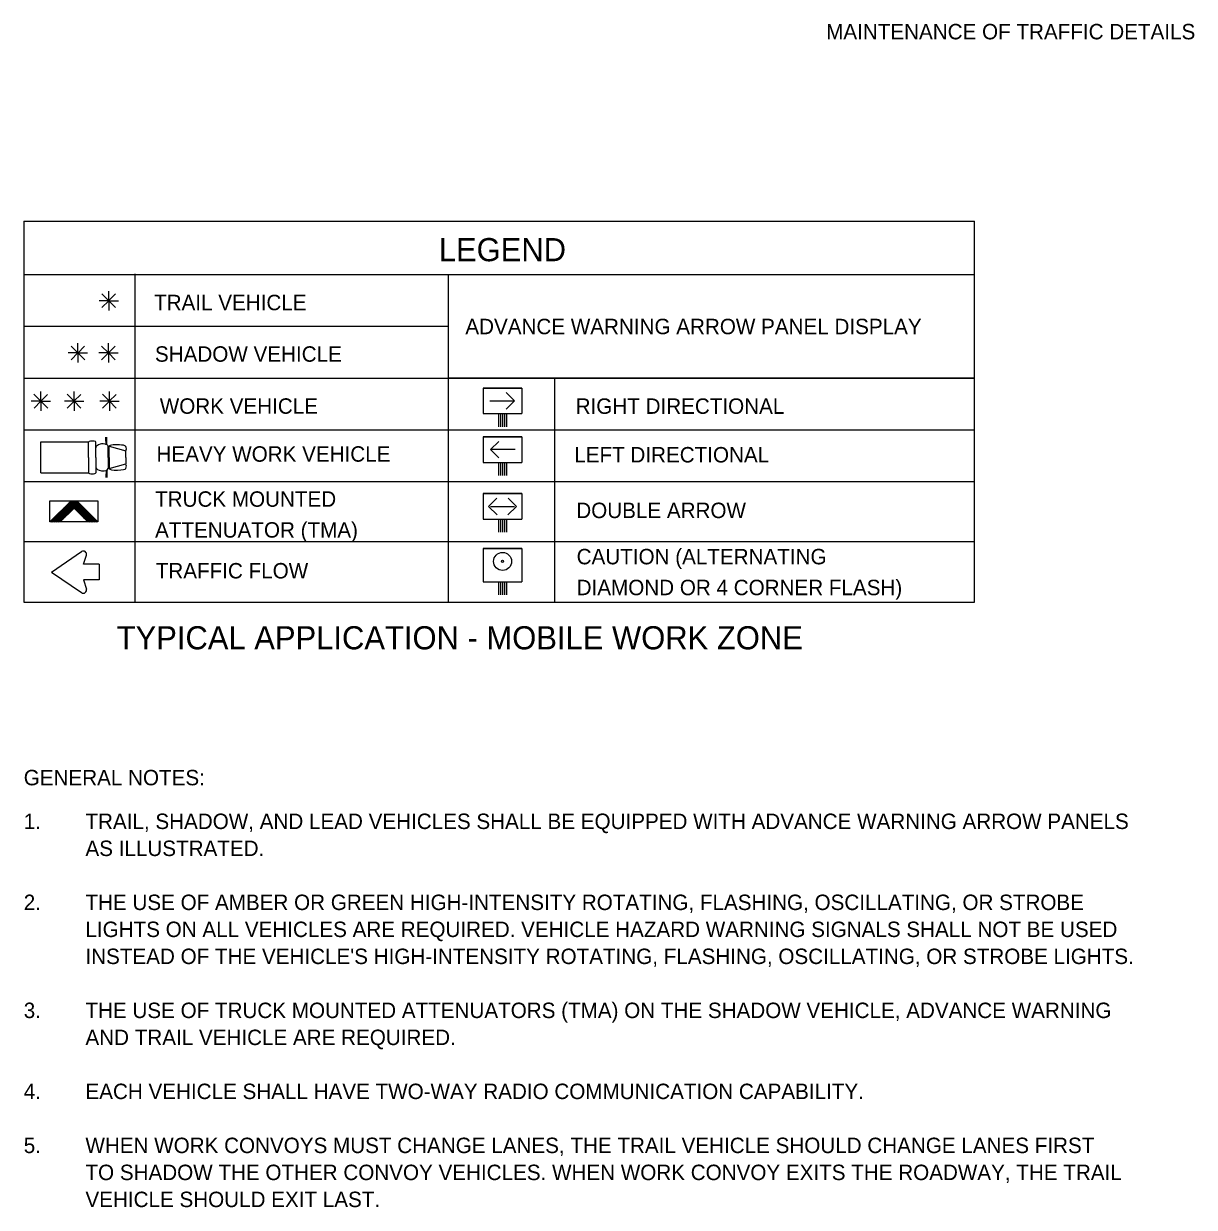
# Model space of a CAD drawing. Extents: x 1373848 to 1374003, y 380642 to 381248.
# Drawn here: x 1373956.39 to 1374001.91, y 381031.39 to 381077.41 of the extents above; entities that cross this region are included whole.
import ezdxf

# ---------------------------------------------------------------- set-up
doc = ezdxf.new("R2010")
doc.units = 0
doc.layers.add('G-ANNO-TEXT', color=7, linetype='Continuous')
doc.layers.add('Working Level 1', color=7, linetype='Continuous')

msp = doc.modelspace()

# ---------------------------------------------------------------- linework, layer by layer
at = {"layer": 'Working Level 1'}
for p, q in [((1373956.388, 381069.735), (1373956.388, 381054.914)), ((1373956.388, 381069.735), (1373993.355, 381069.735)), ((1373993.355, 381054.914), (1373993.355, 381069.735)), ((1373956.388, 381067.655), (1373993.355, 381067.655)), ((1373960.716, 381067.69), (1373960.716, 381054.914)), ((1373960.716, 381067.69), (1373960.716, 381054.914)), ((1373972.892, 381067.655), (1373972.892, 381054.914)), ((1373959.694, 381066.64), (1373959.694, 381067.017)), ((1373959.694, 381066.64), (1373959.318, 381066.64)), ((1373959.694, 381066.64), (1373959.428, 381066.906)), ((1373959.694, 381066.64), (1373959.428, 381066.374)), ((1373959.688, 381066.635), (1373959.954, 381066.901)), ((1373959.694, 381066.64), (1373959.96, 381066.374)), ((1373959.694, 381066.64), (1373959.694, 381066.264)), ((1373959.694, 381066.64), (1373960.07, 381066.64)), ((1373956.388, 381065.644), (1373972.892, 381065.644)), ((1373958.496, 381064.607), (1373958.23, 381064.873)), ((1373958.491, 381064.602), (1373958.758, 381064.868)), ((1373958.496, 381064.607), (1373958.496, 381064.984)), ((1373959.68, 381064.607), (1373959.413, 381064.873)), ((1373959.674, 381064.602), (1373959.941, 381064.868)), ((1373959.68, 381064.607), (1373959.68, 381064.984)), ((1373958.496, 381064.607), (1373958.12, 381064.608)), ((1373958.496, 381064.607), (1373958.231, 381064.341)), ((1373958.496, 381064.607), (1373958.763, 381064.341)), ((1373958.496, 381064.607), (1373958.496, 381064.231)), ((1373958.496, 381064.607), (1373958.873, 381064.607)), ((1373959.68, 381064.607), (1373959.304, 381064.607)), ((1373959.68, 381064.607), (1373959.414, 381064.341)), ((1373959.68, 381064.607), (1373959.946, 381064.341)), ((1373959.68, 381064.607), (1373959.68, 381064.231)), ((1373959.68, 381064.607), (1373960.056, 381064.607)), ((1373956.388, 381063.633), (1373993.355, 381063.633)), ((1373993.355, 381063.633), (1373972.892, 381063.633)), ((1373977.029, 381063.633), (1373977.029, 381054.913)), ((1373957.056, 381062.734), (1373956.789, 381063)), ((1373957.05, 381062.728), (1373957.316, 381062.994)), ((1373957.056, 381062.734), (1373957.056, 381063.11)), ((1373958.345, 381062.734), (1373958.078, 381063)), ((1373958.339, 381062.728), (1373958.605, 381062.994)), ((1373958.345, 381062.734), (1373958.345, 381063.11)), ((1373959.719, 381062.734), (1373959.453, 381063)), ((1373959.713, 381062.728), (1373959.98, 381062.994)), ((1373959.719, 381062.734), (1373959.719, 381063.11)), ((1373974.256, 381063.243), (1373974.256, 381062.248)), ((1373975.761, 381063.243), (1373974.256, 381063.243)), ((1373974.256, 381063.243), (1373975.76, 381063.243)), ((1373975.473, 381062.746), (1373975.154, 381063.065)), ((1373975.761, 381063.243), (1373975.761, 381062.248)), ((1373957.056, 381062.734), (1373956.68, 381062.734)), ((1373957.056, 381062.734), (1373956.79, 381062.468)), ((1373957.056, 381062.734), (1373957.321, 381062.468)), ((1373957.056, 381062.734), (1373957.056, 381062.357)), ((1373957.056, 381062.734), (1373957.432, 381062.734)), ((1373958.345, 381062.734), (1373957.969, 381062.734)), ((1373958.345, 381062.734), (1373958.079, 381062.468)), ((1373958.345, 381062.734), (1373958.611, 381062.468)), ((1373958.345, 381062.734), (1373958.345, 381062.357)), ((1373958.345, 381062.734), (1373958.721, 381062.734)), ((1373959.719, 381062.734), (1373959.343, 381062.734)), ((1373959.719, 381062.734), (1373959.453, 381062.468)), ((1373959.719, 381062.734), (1373959.985, 381062.468)), ((1373959.719, 381062.734), (1373959.719, 381062.357)), ((1373959.719, 381062.734), (1373960.095, 381062.734)), ((1373974.51, 381062.746), (1373975.473, 381062.746)), ((1373975.473, 381062.746), (1373975.146, 381062.419)), ((1373974.256, 381062.248), (1373975.761, 381062.248)), ((1373974.857, 381062.248), (1373974.857, 381061.741)), ((1373974.932, 381062.248), (1373974.932, 381061.741)), ((1373975.008, 381062.248), (1373975.008, 381061.741)), ((1373975.083, 381062.248), (1373975.083, 381061.741)), ((1373975.159, 381062.248), (1373975.159, 381061.741)), ((1373956.388, 381061.622), (1373993.355, 381061.622)), ((1373956.388, 381061.622), (1373972.885, 381061.622)), ((1373957.056, 381061.147), (1373958.911, 381061.147)), ((1373957.056, 381059.947), (1373957.056, 381061.147)), ((1373958.911, 381060.547), (1373958.911, 381061.147)), ((1373959.195, 381060.547), (1373959.195, 381061.147)), ((1373959.578, 381061.182), (1373959.578, 381061.328)), ((1373959.602, 381061.041), (1373959.602, 381061.328)), ((1373959.621, 381061.041), (1373959.621, 381061.328)), ((1373974.256, 381061.35), (1373974.256, 381060.355)), ((1373975.761, 381061.35), (1373974.256, 381061.35)), ((1373974.256, 381061.35), (1373975.76, 381061.35)), ((1373974.542, 381060.853), (1373974.862, 381061.172)), ((1373975.761, 381061.35), (1373975.761, 381060.355)), ((1373958.911, 381060.547), (1373958.911, 381059.947)), ((1373959.195, 381060.547), (1373959.195, 381059.947)), ((1373959.672, 381060.547), (1373959.672, 381060.978)), ((1373959.672, 381060.547), (1373959.672, 381060.115)), ((1373959.711, 381060.978), (1373960.36, 381060.802)), ((1373959.711, 381060.547), (1373959.711, 381060.978)), ((1373959.711, 381060.547), (1373959.711, 381060.115)), ((1373960.36, 381060.547), (1373960.36, 381060.802)), ((1373960.36, 381060.547), (1373960.36, 381060.292)), ((1373975.505, 381060.853), (1373974.542, 381060.853)), ((1373974.542, 381060.853), (1373974.87, 381060.525)), ((1373959.711, 381060.115), (1373960.36, 381060.292)), ((1373974.256, 381060.355), (1373975.761, 381060.355)), ((1373974.857, 381060.355), (1373974.857, 381059.848)), ((1373974.932, 381060.355), (1373974.932, 381059.848)), ((1373975.008, 381060.355), (1373975.008, 381059.848)), ((1373975.083, 381060.355), (1373975.083, 381059.848)), ((1373975.159, 381060.355), (1373975.159, 381059.848)), ((1373957.056, 381059.947), (1373958.911, 381059.947)), ((1373959.578, 381059.912), (1373959.578, 381059.764)), ((1373959.602, 381060.052), (1373959.602, 381059.764)), ((1373959.621, 381060.052), (1373959.621, 381059.764)), ((1373956.388, 381059.612), (1373993.355, 381059.612)), ((1373957.407, 381058.039), (1373958.218, 381058.851)), ((1373959.27, 381058.044), (1373958.467, 381058.847)), ((1373974.256, 381059.141), (1373974.256, 381058.146)), ((1373975.761, 381059.141), (1373974.256, 381059.141)), ((1373974.256, 381059.141), (1373975.76, 381059.141)), ((1373974.467, 381058.644), (1373974.787, 381058.963)), ((1373975.549, 381058.644), (1373975.229, 381058.963)), ((1373975.761, 381059.141), (1373975.761, 381058.146)), ((1373957.813, 381058.039), (1373958.345, 381058.574)), ((1373958.88, 381058.039), (1373958.345, 381058.574)), ((1373974.467, 381058.644), (1373974.794, 381058.316)), ((1373974.542, 381058.644), (1373975.473, 381058.644)), ((1373975.549, 381058.644), (1373975.221, 381058.316)), ((1373974.256, 381058.146), (1373975.761, 381058.146)), ((1373974.857, 381058.146), (1373974.857, 381057.64)), ((1373974.932, 381058.146), (1373974.932, 381057.64)), ((1373975.008, 381058.146), (1373975.008, 381057.64)), ((1373975.083, 381058.146), (1373975.083, 381057.64)), ((1373975.159, 381058.146), (1373975.159, 381057.64)), ((1373956.388, 381057.275), (1373993.355, 381057.275)), ((1373957.475, 381056.087), (1373958.638, 381056.885)), ((1373974.256, 381057), (1373974.256, 381055.706)), ((1373975.761, 381057), (1373974.256, 381057)), ((1373974.256, 381057), (1373975.76, 381057)), ((1373975.761, 381057), (1373975.761, 381055.706)), ((1373958.711, 381056.392), (1373958.825, 381056.745)), ((1373957.475, 381056.087), (1373958.638, 381055.29)), ((1373959.318, 381056.392), (1373958.711, 381056.392)), ((1373959.318, 381056.392), (1373959.318, 381055.783)), ((1373959.318, 381055.783), (1373958.711, 381055.783)), ((1373958.711, 381055.783), (1373958.825, 381055.43)), ((1373974.256, 381055.706), (1373975.761, 381055.706)), ((1373974.857, 381055.706), (1373974.857, 381055.199)), ((1373974.932, 381055.706), (1373974.932, 381055.199)), ((1373975.008, 381055.706), (1373975.008, 381055.199)), ((1373975.083, 381055.706), (1373975.083, 381055.199)), ((1373975.159, 381055.706), (1373975.159, 381055.199)), ((1373956.388, 381054.914), (1373993.355, 381054.914))]:
    msp.add_line(p, q, dxfattribs=at)
msp.add_lwpolyline([(1373959.27, 381058.853), (1373959.27, 381058.039), (1373957.407, 381058.039), (1373957.407, 381058.853)], close=True, dxfattribs=at)
for points in [[(1373957.448, 381058.08), (1373958.579, 381058.733)], [(1373957.548, 381058.18), (1373958.553, 381058.76)], [(1373957.648, 381058.281), (1373958.526, 381058.787)], [(1373957.749, 381058.381), (1373958.499, 381058.814)], [(1373957.849, 381058.481), (1373958.472, 381058.841)], [(1373957.949, 381058.581), (1373958.41, 381058.848)], [(1373958.049, 381058.682), (1373958.338, 381058.849)], [(1373958.148, 381058.781), (1373958.268, 381058.85)], [(1373958.357, 381058.563), (1373958.606, 381058.707)], [(1373957.451, 381058.039), (1373958.304, 381058.532)], [(1373957.524, 381058.039), (1373958.209, 381058.435)], [(1373957.597, 381058.039), (1373958.114, 381058.337)], [(1373958.384, 381058.536), (1373958.633, 381058.68)], [(1373958.411, 381058.509), (1373958.66, 381058.652)], [(1373958.438, 381058.482), (1373958.687, 381058.626)], [(1373958.465, 381058.455), (1373958.714, 381058.599)], [(1373958.492, 381058.428), (1373958.741, 381058.572)], [(1373958.518, 381058.401), (1373958.767, 381058.545)], [(1373958.545, 381058.375), (1373958.794, 381058.518)], [(1373958.572, 381058.347), (1373958.82, 381058.491)], [(1373958.599, 381058.321), (1373958.848, 381058.464)], [(1373958.626, 381058.294), (1373958.874, 381058.437)], [(1373958.653, 381058.267), (1373958.901, 381058.41)], [(1373958.68, 381058.24), (1373958.928, 381058.383)], [(1373958.706, 381058.213), (1373958.955, 381058.356)], [(1373958.733, 381058.186), (1373958.982, 381058.329)], [(1373958.76, 381058.159), (1373959.008, 381058.303)], [(1373958.787, 381058.132), (1373959.035, 381058.276)], [(1373958.814, 381058.105), (1373959.062, 381058.248)], [(1373957.671, 381058.039), (1373958.018, 381058.239)], [(1373957.745, 381058.039), (1373957.922, 381058.142)], [(1373957.818, 381058.039), (1373957.826, 381058.044)], [(1373958.84, 381058.078), (1373959.089, 381058.222)], [(1373958.868, 381058.052), (1373959.115, 381058.194)], [(1373958.919, 381058.039), (1373959.143, 381058.168)], [(1373958.993, 381058.039), (1373959.169, 381058.141)], [(1373959.067, 381058.039), (1373959.196, 381058.114)], [(1373959.14, 381058.039), (1373959.223, 381058.087)], [(1373959.214, 381058.039), (1373959.249, 381058.06)]]:
    msp.add_lwpolyline(points, dxfattribs=at)
for radius in [0.351, 0.0437]:
    msp.add_circle((1373975.008, 381056.503), radius, dxfattribs=at)
for centre, radius, start, end in [((1373960.201, 381060.886), 0.18, 331.8801, 28.1199), ((1373960.201, 381060.207), 0.18, 331.8801, 28.1199), ((1373958.708, 381056.784), 0.123, 342.1824, 124.4455), ((1373958.708, 381055.391), 0.123, 235.5546, 17.8176)]:
    msp.add_arc(centre, radius, start, end, dxfattribs=at)
for centre, major_axis, ratio, start_param, end_param in [((1373959.053, 381061.146), (0.142, 0), 0.269913, 0, 3.141593), ((1373959.433, 381060.949), (0.238, 0.029), 0.503092, 0, 3.141593), ((1373960.035, 381060.974), (0.324, -0.004), 0.2034, 0, 3.141593), ((1373959.433, 381060.144), (0.238, -0.029), 0.503092, 3.141593, 6.283185), ((1373960.035, 381060.118), (0.324, 0.004), 0.2034, 3.141593, 6.283185), ((1373959.053, 381059.947), (0.142, 0), 0.269913, 3.141593, 6.283185)]:
    msp.add_ellipse(centre, major_axis=major_axis, ratio=ratio, start_param=start_param, end_param=end_param, dxfattribs=at)

# ---------------------------------------------------------------- texts
at = {"layer": 'G-ANNO-TEXT'}
msp.add_text('MAINTENANCE OF TRAFFIC DETAILS', height=0.6, dxfattribs=at).set_placement((1373987.593, 381076.802))
at = {"layer": 'Working Level 1'}
for s, height, p in [('LEGEND', 0.9, (1373972.529, 381068.175)), ('TRAIL VEHICLE', 0.6, (1373961.458, 381066.27)), ('ADVANCE WARNING ARROW PANEL DISPLAY', 0.6, (1373973.562, 381065.337)), ('SHADOW VEHICLE', 0.6, (1373961.493, 381064.267)), ('WORK VEHICLE', 0.6, (1373961.68, 381062.244)), ('RIGHT DIRECTIONAL', 0.6, (1373977.853, 381062.241)), ('HEAVY WORK VEHICLE', 0.6, (1373961.554, 381060.38)), ('LEFT DIRECTIONAL', 0.6, (1373977.798, 381060.351)), ('TRUCK MOUNTED ', 0.6, (1373961.497, 381058.628)), ('DOUBLE ARROW', 0.6, (1373977.877, 381058.188)), ('ATTENUATOR (TMA)', 0.6, (1373961.497, 381057.428)), ('CAUTION (ALTERNATING ', 0.6, (1373977.891, 381056.39)), ('TRAFFIC FLOW', 0.6, (1373961.524, 381055.841)), ('DIAMOND OR 4 CORNER FLASH)', 0.6, (1373977.891, 381055.19)), ('TYPICAL APPLICATION - MOBILE WORK ZONE', 0.9, (1373960.004, 381053.084)), ('GENERAL NOTES:', 0.6, (1373956.39, 381047.798)), ('1. ', 0.6, (1373956.39, 381046.098)), ('TRAIL, SHADOW, AND LEAD VEHICLES SHALL BE EQUIPPED WITH ADVANCE WARNING ARROW PANELS', 0.6, (1373958.79, 381046.098)), ('AS ILLUSTRATED. ', 0.6, (1373958.79, 381045.048)), ('2.', 0.6, (1373956.39, 381042.948)), ('THE USE OF AMBER OR GREEN HIGH-INTENSITY ROTATING, FLASHING, OSCILLATING, OR STROBE ', 0.6, (1373958.79, 381042.948)), ('LIGHTS ON ALL VEHICLES ARE REQUIRED. VEHICLE HAZARD WARNING SIGNALS SHALL NOT BE USED ', 0.6, (1373958.79, 381041.898)), ("INSTEAD OF THE VEHICLE'S HIGH-INTENSITY ROTATING, FLASHING, OSCILLATING, OR STROBE LIGHTS.", 0.6, (1373958.79, 381040.848)), ('THE USE OF TRUCK MOUNTED ATTENUATORS (TMA) ON THE SHADOW VEHICLE, ADVANCE WARNING', 0.6, (1373958.79, 381038.748)), ('3. ', 0.6, (1373956.39, 381038.748)), ('AND TRAIL VEHICLE ARE REQUIRED.', 0.6, (1373958.79, 381037.698)), ('4. ', 0.6, (1373956.39, 381035.598)), ('EACH VEHICLE SHALL HAVE TWO-WAY RADIO COMMUNICATION CAPABILITY. ', 0.6, (1373958.79, 381035.598)), ('5. ', 0.6, (1373956.39, 381033.498)), ('WHEN WORK CONVOYS MUST CHANGE LANES, THE TRAIL VEHICLE SHOULD CHANGE LANES FIRST ', 0.6, (1373958.79, 381033.498)), ('TO SHADOW THE OTHER CONVOY VEHICLES. WHEN WORK CONVOY EXITS THE ROADWAY, THE TRAIL', 0.6, (1373958.79, 381032.448)), ('VEHICLE SHOULD EXIT LAST.', 0.6, (1373958.79, 381031.398))]:
    msp.add_text(s, height=height, dxfattribs=at).set_placement(p)

doc.saveas('drawing.dxf')
